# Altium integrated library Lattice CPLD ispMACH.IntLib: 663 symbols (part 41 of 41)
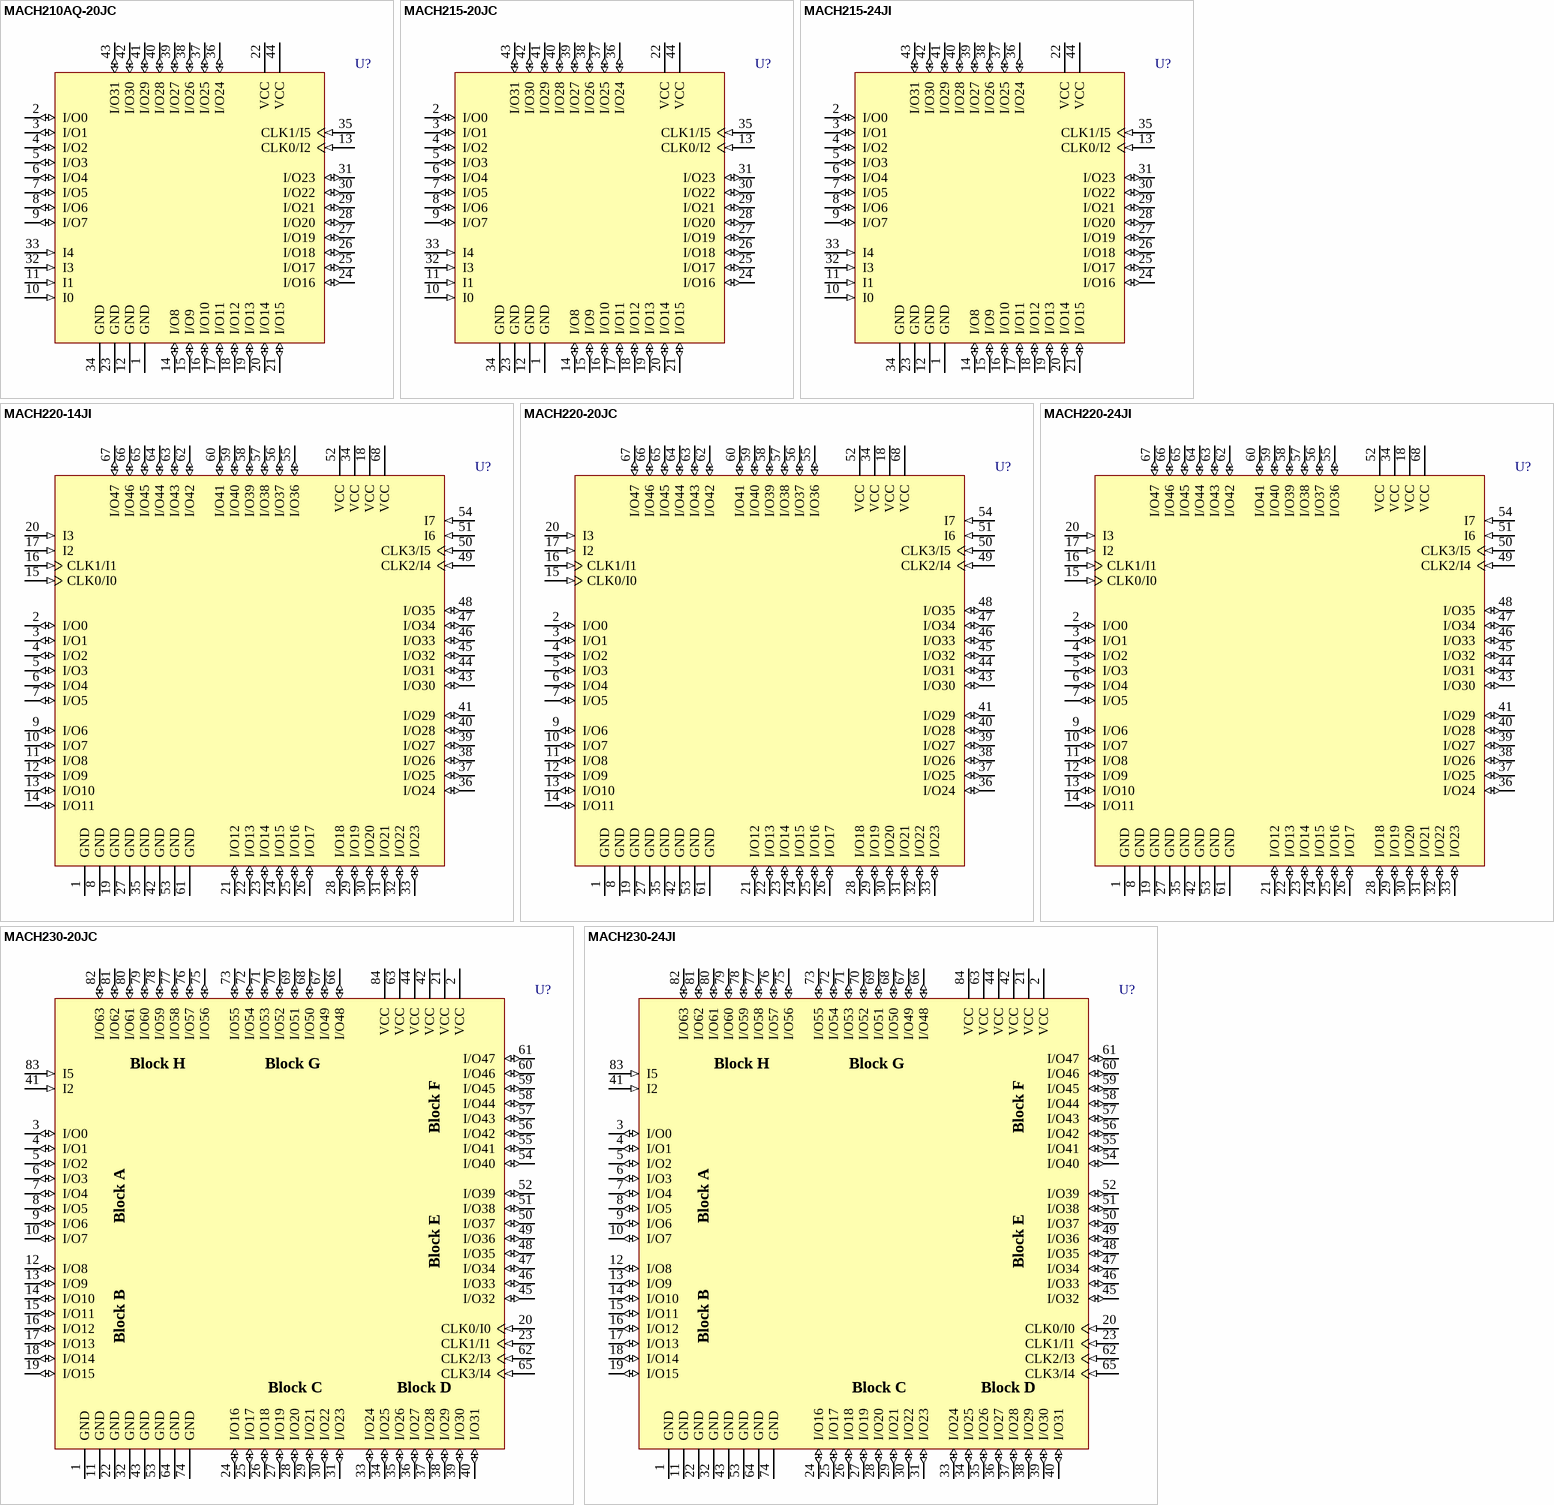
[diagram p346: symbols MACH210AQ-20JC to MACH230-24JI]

## MACH220-24JI
designator U?
High-Density EE CMOS Programmable Logic
footprint PLCC68_N (Leaded Chip Carrier, 68-Leads, Body 24x24mm, Pitch 1.27mm, IPC Medium Density)
footprint PLCC68_L (Leaded Chip Carrier, 68-Leads, Body 24x24mm, Pitch 1.27mm, IPC High Density)
footprint PLCC68_M (Leaded Chip Carrier, 68-Leads, Body 24x24mm, Pitch 1.27mm, IPC Low Density)
3D model MACH220-PLCC68 (68-Pin Leaded Chip Carrier 1.27 mm Pitch)
pins: 1 GND (power), 2 I/O0 (io), 3 I/O1 (io), 4 I/O2 (io), 5 I/O3 (io), 6 I/O4 (io), 7 I/O5 (io), 8 GND (power), 9 I/O6 (io), 10 I/O7 (io), 11 I/O8 (io), 12 I/O9 (io), 13 I/O10 (io), 14 I/O11 (io), 15 CLK0/I0 (in), 16 CLK1/I1 (in), 17 I2 (in), 18 VCC (power), 19 GND (power), 20 I3 (in), 21 I/O12 (io), 22 I/O13 (io), 23 I/O14 (io), 24 I/O15 (io), 25 I/O16 (io), 26 I/O17 (io), 27 GND (power), 28 I/O18 (io), 29 I/O19 (io), 30 I/O20 (io), 31 I/O21 (io), 32 I/O22 (io), 33 I/O23 (io), 34 VCC (power), 35 GND (power), 36 I/O24 (io), 37 I/O25 (io), 38 I/O26 (io), 39 I/O27 (io), 40 I/O28 (io), 41 I/O29 (io), 42 GND (power), 43 I/O30 (io), 44 I/O31 (io), 45 I/O32 (io), 46 I/O33 (io), 47 I/O34 (io), 48 I/O35 (io), 49 CLK2/I4 (in), 50 CLK3/I5 (in), 51 I6 (in), 52 VCC (power), 53 GND (power), 54 I7 (in), 55 I/O36 (io), 56 I/O37 (io), 57 I/O38 (io), 58 I/O39 (io), 59 I/O40 (io), 60 I/O41 (io), 61 GND (power), 62 I/O42 (io), 63 I/O43 (io), 64 I/O44 (io), 65 I/O45 (io), 66 I/O46 (io), 67 I/O47 (io), 68 VCC (power)

## MACH230-20JC
designator U?
High-Density EE CMOS Programmable Logic
footprint PLCC84_N (Leaded Chip Carrier, 84-Leads, Body 29.3x29.3mm, Pitch 1.27mm, IPC Medium Density)
footprint PLCC84_L (Leaded Chip Carrier, 84-Leads, Body 29.3x29.3mm, Pitch 1.27mm, IPC High Density)
footprint PLCC84_M (Leaded Chip Carrier, 84-Leads, Body 29.3x29.3mm, Pitch 1.27mm, IPC Low Density)
3D model MACH230-PLCC84 (84-Pin Leaded Chip Carrier 1.27 mm Pitch)
pins: 1 GND (power), 2 VCC (power), 3 I/O0 (io), 4 I/O1 (io), 5 I/O2 (io), 6 I/O3 (io), 7 I/O4 (io), 8 I/O5 (io), 9 I/O6 (io), 10 I/O7 (io), 11 GND (power), 12 I/O8 (io), 13 I/O9 (io), 14 I/O10 (io), 15 I/O11 (io), 16 I/O12 (io), 17 I/O13 (io), 18 I/O14 (io), 19 I/O15 (io), 20 CLK0/I0 (in), 21 VCC (power), 22 GND (power), 23 CLK1/I1 (in), 24 I/O16 (io), 25 I/O17 (io), 26 I/O18 (io), 27 I/O19 (io), 28 I/O20 (io), 29 I/O21 (io), 30 I/O22 (io), 31 I/O23 (io), 32 GND (power), 33 I/O24 (io), 34 I/O25 (io), 35 I/O26 (io), 36 I/O27 (io), 37 I/O28 (io), 38 I/O29 (io), 39 I/O30 (io), 40 I/O31 (io), 41 I2 (in), 42 VCC (power), 43 GND (power), 44 VCC (power), 45 I/O32 (io), 46 I/O33 (io), 47 I/O34 (io), 48 I/O35 (io), 49 I/O36 (io), 50 I/O37 (io), 51 I/O38 (io), 52 I/O39 (io), 53 GND (power), 54 I/O40 (io), 55 I/O41 (io), 56 I/O42 (io), 57 I/O43 (io), 58 I/O44 (io), 59 I/O45 (io), 60 I/O46 (io), 61 I/O47 (io), 62 CLK2/I3 (in), 63 VCC (power), 64 GND (power), 65 CLK3/I4 (in), 66 I/O48 (io), 67 I/O49 (io), 68 I/O50 (io), 69 I/O51 (io), 70 I/O52 (io), 71 I/O53 (io), 72 I/O54 (io), 73 I/O55 (io), 74 GND (power), 75 I/O56 (io), 76 I/O57 (io), 77 I/O58 (io), 78 I/O59 (io), 79 I/O60 (io), 80 I/O61 (io), 81 I/O62 (io), 82 I/O63 (io), 83 I5 (in), 84 VCC (power)

## MACH230-24JI
designator U?
High-Density EE CMOS Programmable Logic
footprint PLCC84_N (Leaded Chip Carrier, 84-Leads, Body 29.3x29.3mm, Pitch 1.27mm, IPC Medium Density)
footprint PLCC84_L (Leaded Chip Carrier, 84-Leads, Body 29.3x29.3mm, Pitch 1.27mm, IPC High Density)
footprint PLCC84_M (Leaded Chip Carrier, 84-Leads, Body 29.3x29.3mm, Pitch 1.27mm, IPC Low Density)
3D model MACH230-PLCC84 (84-Pin Leaded Chip Carrier 1.27 mm Pitch)
pins: 1 GND (power), 2 VCC (power), 3 I/O0 (io), 4 I/O1 (io), 5 I/O2 (io), 6 I/O3 (io), 7 I/O4 (io), 8 I/O5 (io), 9 I/O6 (io), 10 I/O7 (io), 11 GND (power), 12 I/O8 (io), 13 I/O9 (io), 14 I/O10 (io), 15 I/O11 (io), 16 I/O12 (io), 17 I/O13 (io), 18 I/O14 (io), 19 I/O15 (io), 20 CLK0/I0 (in), 21 VCC (power), 22 GND (power), 23 CLK1/I1 (in), 24 I/O16 (io), 25 I/O17 (io), 26 I/O18 (io), 27 I/O19 (io), 28 I/O20 (io), 29 I/O21 (io), 30 I/O22 (io), 31 I/O23 (io), 32 GND (power), 33 I/O24 (io), 34 I/O25 (io), 35 I/O26 (io), 36 I/O27 (io), 37 I/O28 (io), 38 I/O29 (io), 39 I/O30 (io), 40 I/O31 (io), 41 I2 (in), 42 VCC (power), 43 GND (power), 44 VCC (power), 45 I/O32 (io), 46 I/O33 (io), 47 I/O34 (io), 48 I/O35 (io), 49 I/O36 (io), 50 I/O37 (io), 51 I/O38 (io), 52 I/O39 (io), 53 GND (power), 54 I/O40 (io), 55 I/O41 (io), 56 I/O42 (io), 57 I/O43 (io), 58 I/O44 (io), 59 I/O45 (io), 60 I/O46 (io), 61 I/O47 (io), 62 CLK2/I3 (in), 63 VCC (power), 64 GND (power), 65 CLK3/I4 (in), 66 I/O48 (io), 67 I/O49 (io), 68 I/O50 (io), 69 I/O51 (io), 70 I/O52 (io), 71 I/O53 (io), 72 I/O54 (io), 73 I/O55 (io), 74 GND (power), 75 I/O56 (io), 76 I/O57 (io), 77 I/O58 (io), 78 I/O59 (io), 79 I/O60 (io), 80 I/O61 (io), 81 I/O62 (io), 82 I/O63 (io), 83 I5 (in), 84 VCC (power)

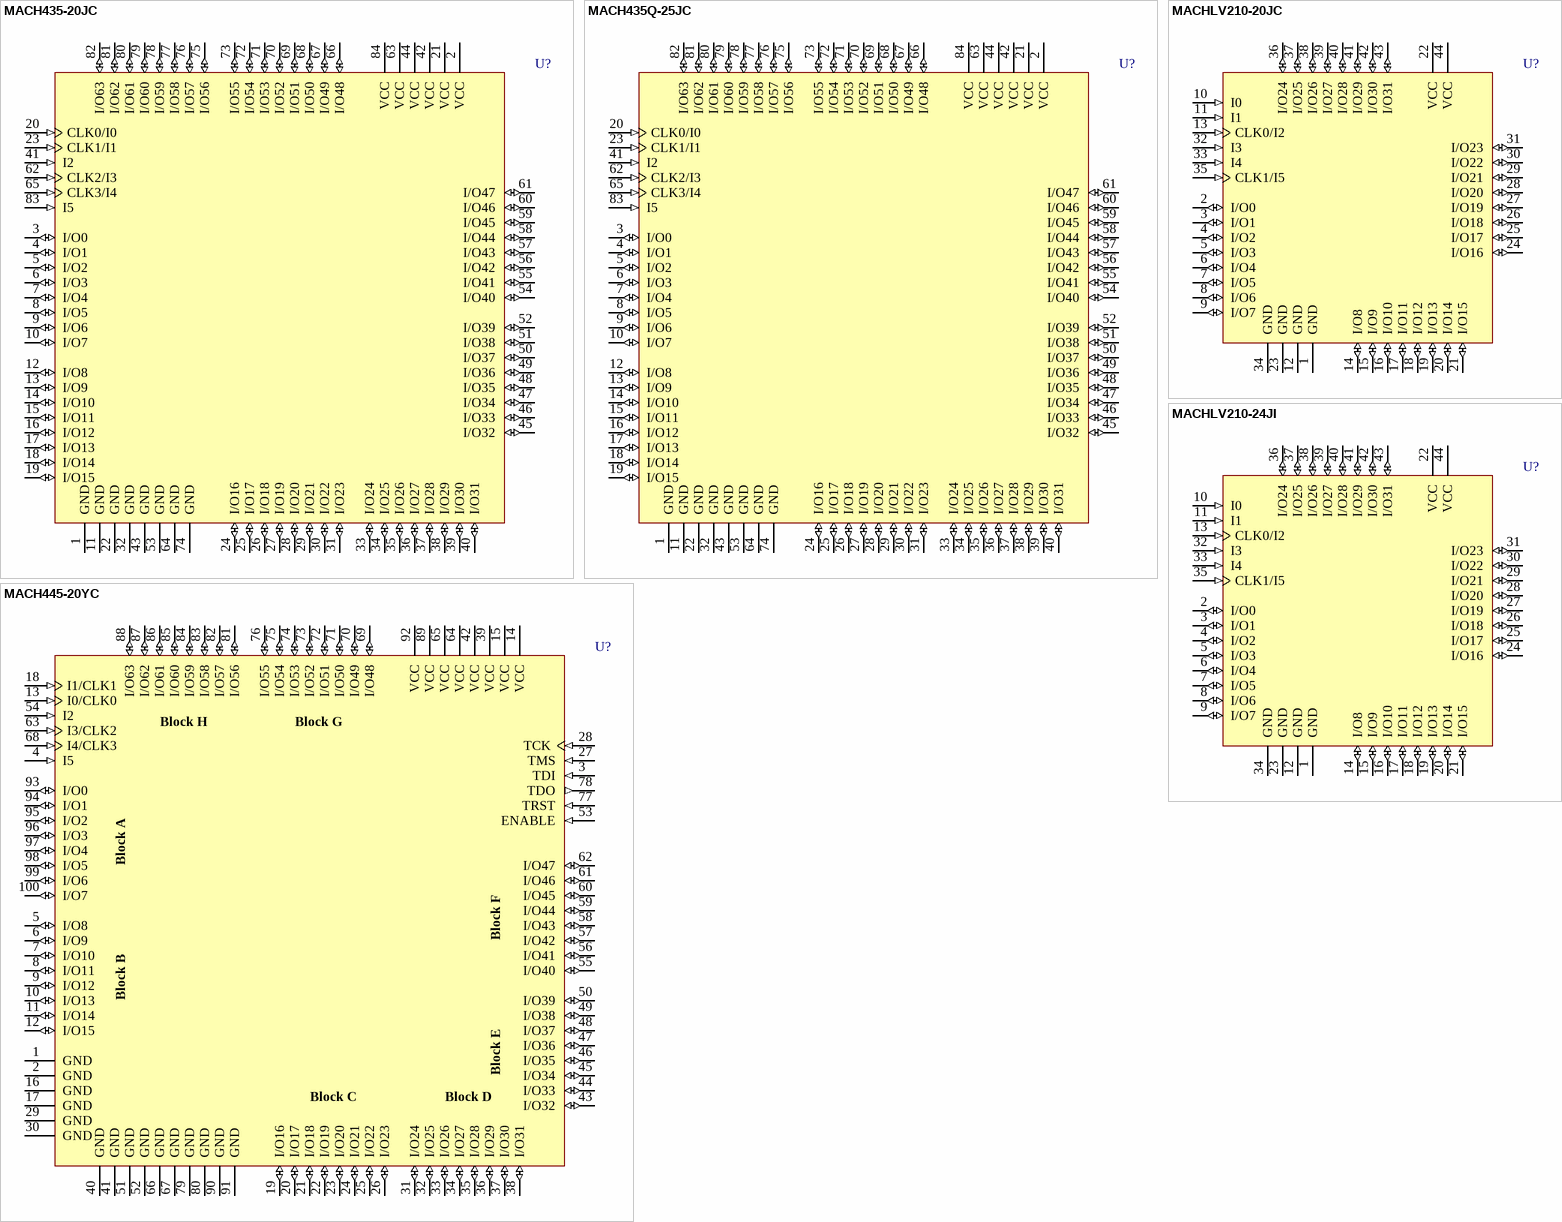
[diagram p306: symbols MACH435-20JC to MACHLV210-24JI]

## MACH435-20JC
designator U?
High-Density EE CMOS Programmable Logic
footprint PLCC84_N (Leaded Chip Carrier, 84-Leads, Body 29.3x29.3mm, Pitch 1.27mm, IPC Medium Density)
footprint PLCC84_L (Leaded Chip Carrier, 84-Leads, Body 29.3x29.3mm, Pitch 1.27mm, IPC High Density)
footprint PLCC84_M (Leaded Chip Carrier, 84-Leads, Body 29.3x29.3mm, Pitch 1.27mm, IPC Low Density)
3D model MACH435Q-PLCC84 (84-Pin Leaded Chip Carrier 1.27 mm Pitch)
pins: 1 GND (power), 2 VCC (power), 3 I/O0 (io), 4 I/O1 (io), 5 I/O2 (io), 6 I/O3 (io), 7 I/O4 (io), 8 I/O5 (io), 9 I/O6 (io), 10 I/O7 (io), 11 GND (power), 12 I/O8 (io), 13 I/O9 (io), 14 I/O10 (io), 15 I/O11 (io), 16 I/O12 (io), 17 I/O13 (io), 18 I/O14 (io), 19 I/O15 (io), 20 CLK0/I0 (in), 21 VCC (power), 22 GND (power), 23 CLK1/I1 (in), 24 I/O16 (io), 25 I/O17 (io), 26 I/O18 (io), 27 I/O19 (io), 28 I/O20 (io), 29 I/O21 (io), 30 I/O22 (io), 31 I/O23 (io), 32 GND (power), 33 I/O24 (io), 34 I/O25 (io), 35 I/O26 (io), 36 I/O27 (io), 37 I/O28 (io), 38 I/O29 (io), 39 I/O30 (io), 40 I/O31 (io), 41 I2 (in), 42 VCC (power), 43 GND (power), 44 VCC (power), 45 I/O32 (io), 46 I/O33 (io), 47 I/O34 (io), 48 I/O35 (io), 49 I/O36 (io), 50 I/O37 (io), 51 I/O38 (io), 52 I/O39 (io), 53 GND (power), 54 I/O40 (io), 55 I/O41 (io), 56 I/O42 (io), 57 I/O43 (io), 58 I/O44 (io), 59 I/O45 (io), 60 I/O46 (io), 61 I/O47 (io), 62 CLK2/I3 (in), 63 VCC (power), 64 GND (power), 65 CLK3/I4 (in), 66 I/O48 (io), 67 I/O49 (io), 68 I/O50 (io), 69 I/O51 (io), 70 I/O52 (io), 71 I/O53 (io), 72 I/O54 (io), 73 I/O55 (io), 74 GND (power), 75 I/O56 (io), 76 I/O57 (io), 77 I/O58 (io), 78 I/O59 (io), 79 I/O60 (io), 80 I/O61 (io), 81 I/O62 (io), 82 I/O63 (io), 83 I5 (in), 84 VCC (power)

## MACH435Q-25JC
designator U?
High-Density EE CMOS Programmable Logic
footprint PLCC84_N (Leaded Chip Carrier, 84-Leads, Body 29.3x29.3mm, Pitch 1.27mm, IPC Medium Density)
footprint PLCC84_L (Leaded Chip Carrier, 84-Leads, Body 29.3x29.3mm, Pitch 1.27mm, IPC High Density)
footprint PLCC84_M (Leaded Chip Carrier, 84-Leads, Body 29.3x29.3mm, Pitch 1.27mm, IPC Low Density)
3D model MACH435Q-PLCC84 (84-Pin Leaded Chip Carrier 1.27 mm Pitch)
pins: 1 GND (power), 2 VCC (power), 3 I/O0 (io), 4 I/O1 (io), 5 I/O2 (io), 6 I/O3 (io), 7 I/O4 (io), 8 I/O5 (io), 9 I/O6 (io), 10 I/O7 (io), 11 GND (power), 12 I/O8 (io), 13 I/O9 (io), 14 I/O10 (io), 15 I/O11 (io), 16 I/O12 (io), 17 I/O13 (io), 18 I/O14 (io), 19 I/O15 (io), 20 CLK0/I0 (in), 21 VCC (power), 22 GND (power), 23 CLK1/I1 (in), 24 I/O16 (io), 25 I/O17 (io), 26 I/O18 (io), 27 I/O19 (io), 28 I/O20 (io), 29 I/O21 (io), 30 I/O22 (io), 31 I/O23 (io), 32 GND (power), 33 I/O24 (io), 34 I/O25 (io), 35 I/O26 (io), 36 I/O27 (io), 37 I/O28 (io), 38 I/O29 (io), 39 I/O30 (io), 40 I/O31 (io), 41 I2 (in), 42 VCC (power), 43 GND (power), 44 VCC (power), 45 I/O32 (io), 46 I/O33 (io), 47 I/O34 (io), 48 I/O35 (io), 49 I/O36 (io), 50 I/O37 (io), 51 I/O38 (io), 52 I/O39 (io), 53 GND (power), 54 I/O40 (io), 55 I/O41 (io), 56 I/O42 (io), 57 I/O43 (io), 58 I/O44 (io), 59 I/O45 (io), 60 I/O46 (io), 61 I/O47 (io), 62 CLK2/I3 (in), 63 VCC (power), 64 GND (power), 65 CLK3/I4 (in), 66 I/O48 (io), 67 I/O49 (io), 68 I/O50 (io), 69 I/O51 (io), 70 I/O52 (io), 71 I/O53 (io), 72 I/O54 (io), 73 I/O55 (io), 74 GND (power), 75 I/O56 (io), 76 I/O57 (io), 77 I/O58 (io), 78 I/O59 (io), 79 I/O60 (io), 80 I/O61 (io), 81 I/O62 (io), 82 I/O63 (io), 83 I5 (in), 84 VCC (power)

## MACH445-20YC
designator U?
High-Density EE CMOS Programmable Logic
footprint PQFP100_N (QFP, 100-Leads, Body 20x14mm, Pitch 0.65mm, IPC Medium Density)
footprint PQFP100_L (QFP, 100-Leads, Body 20x14mm, Pitch 0.65mm, IPC High Density)
footprint PQFP100_M (QFP, 100-Leads, Body 20x14mm, Pitch 0.65mm, IPC Low Density)
3D model PQFP-100 (100-Pin Quad Flat Pack Rectangular 0.65 mm Pitch)
pins: 1 GND (power), 2 GND (power), 3 TDI (in), 4 I5 (in), 5 I/O8 (io), 6 I/O9 (io), 7 I/O10 (io), 8 I/O11 (io), 9 I/O12 (io), 10 I/O13 (io), 11 I/O14 (io), 12 I/O15 (io), 13 I0/CLK0 (in), 14 VCC (power), 15 VCC (power), 16 GND (power), 17 GND (power), 18 I1/CLK1 (in), 19 I/O16 (io), 20 I/O17 (io), 21 I/O18 (io), 22 I/O19 (io), 23 I/O20 (io), 24 I/O21 (io), 25 I/O22 (io), 26 I/O23 (io), 27 TMS (in), 28 TCK (in), 29 GND (power), 30 GND (power), 31 I/O24 (io), 32 I/O25 (io), 33 I/O26 (io), 34 I/O27 (io), 35 I/O28 (io), 36 I/O29 (io), 37 I/O30 (io), 38 I/O31 (io), 39 VCC (power), 40 GND (power), 41 GND (power), 42 VCC (power), 43 I/O32 (io), 44 I/O33 (io), 45 I/O34 (io), 46 I/O35 (io), 47 I/O36 (io), 48 I/O37 (io), 49 I/O38 (io), 50 I/O39 (io), 51 GND (power), 52 GND (power), 53 ENABLE (in), 54 I2 (in), 55 I/O40 (io), 56 I/O41 (io), 57 I/O42 (io), 58 I/O43 (io), 59 I/O44 (io), 60 I/O45 (io), 61 I/O46 (io), 62 I/O47 (io), 63 I3/CLK2 (in), 64 VCC (power), 65 VCC (power), 66 GND (power), 67 GND (power), 68 I4/CLK3 (in), 69 I/O48 (io), 70 I/O49 (io), 71 I/O50 (io), 72 I/O51 (io), 73 I/O52 (io), 74 I/O53 (io), 75 I/O54 (io), 76 I/O55 (io), 77 TRST (in), 78 TDO (out), 79 GND (power), 80 GND (power), 81 I/O56 (io), 82 I/O57 (io), 83 I/O58 (io), 84 I/O59 (io), 85 I/O60 (io), 86 I/O61 (io), 87 I/O62 (io), 88 I/O63 (io), 89 VCC (power), 90 GND (power), 91 GND (power), 92 VCC (power), 93 I/O0 (io), 94 I/O1 (io), 95 I/O2 (io), 96 I/O3 (io), 97 I/O4 (io), 98 I/O5 (io), 99 I/O6 (io), 100 I/O7 (io)

## MACHLV210-20JC
designator U?
High-Density EE CMOS Programmable Logic
footprint PLCC44_N (Leaded Chip Carrier, 44-Leads, Body 16.6x16.6mm, Pitch 1.27mm, IPC Medium Density)
footprint PLCC44_L (Leaded Chip Carrier, 44-Leads, Body 16.6x16.6mm, Pitch 1.27mm, IPC High Density)
footprint PLCC44_M (Leaded Chip Carrier, 44-Leads, Body 16.6x16.6mm, Pitch 1.27mm, IPC Low Density)
3D model MACHLV210-PLCC44 (44-Pin Leaded Chip Carrier 1.27 mm Pitch)
pins: 1 GND (power), 2 I/O0 (io), 3 I/O1 (io), 4 I/O2 (io), 5 I/O3 (io), 6 I/O4 (io), 7 I/O5 (io), 8 I/O6 (io), 9 I/O7 (io), 10 I0 (in), 11 I1 (in), 12 GND (power), 13 CLK0/I2 (in), 14 I/O8 (io), 15 I/O9 (io), 16 I/O10 (io), 17 I/O11 (io), 18 I/O12 (io), 19 I/O13 (io), 20 I/O14 (io), 21 I/O15 (io), 22 VCC (power), 23 GND (power), 24 I/O16 (io), 25 I/O17 (io), 26 I/O18 (io), 27 I/O19 (io), 28 I/O20 (io), 29 I/O21 (io), 30 I/O22 (io), 31 I/O23 (io), 32 I3 (in), 33 I4 (in), 34 GND (power), 35 CLK1/I5 (in), 36 I/O24 (io), 37 I/O25 (io), 38 I/O26 (io), 39 I/O27 (io), 40 I/O28 (io), 41 I/O29 (io), 42 I/O30 (io), 43 I/O31 (io), 44 VCC (power)

## MACHLV210-24JI
designator U?
High-Density EE CMOS Programmable Logic
footprint PLCC44_N (Leaded Chip Carrier, 44-Leads, Body 16.6x16.6mm, Pitch 1.27mm, IPC Medium Density)
footprint PLCC44_L (Leaded Chip Carrier, 44-Leads, Body 16.6x16.6mm, Pitch 1.27mm, IPC High Density)
footprint PLCC44_M (Leaded Chip Carrier, 44-Leads, Body 16.6x16.6mm, Pitch 1.27mm, IPC Low Density)
3D model MACHLV210-PLCC44 (44-Pin Leaded Chip Carrier 1.27 mm Pitch)
pins: 1 GND (power), 2 I/O0 (io), 3 I/O1 (io), 4 I/O2 (io), 5 I/O3 (io), 6 I/O4 (io), 7 I/O5 (io), 8 I/O6 (io), 9 I/O7 (io), 10 I0 (in), 11 I1 (in), 12 GND (power), 13 CLK0/I2 (in), 14 I/O8 (io), 15 I/O9 (io), 16 I/O10 (io), 17 I/O11 (io), 18 I/O12 (io), 19 I/O13 (io), 20 I/O14 (io), 21 I/O15 (io), 22 VCC (power), 23 GND (power), 24 I/O16 (io), 25 I/O17 (io), 26 I/O18 (io), 27 I/O19 (io), 28 I/O20 (io), 29 I/O21 (io), 30 I/O22 (io), 31 I/O23 (io), 32 I3 (in), 33 I4 (in), 34 GND (power), 35 CLK1/I5 (in), 36 I/O24 (io), 37 I/O25 (io), 38 I/O26 (io), 39 I/O27 (io), 40 I/O28 (io), 41 I/O29 (io), 42 I/O30 (io), 43 I/O31 (io), 44 VCC (power)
